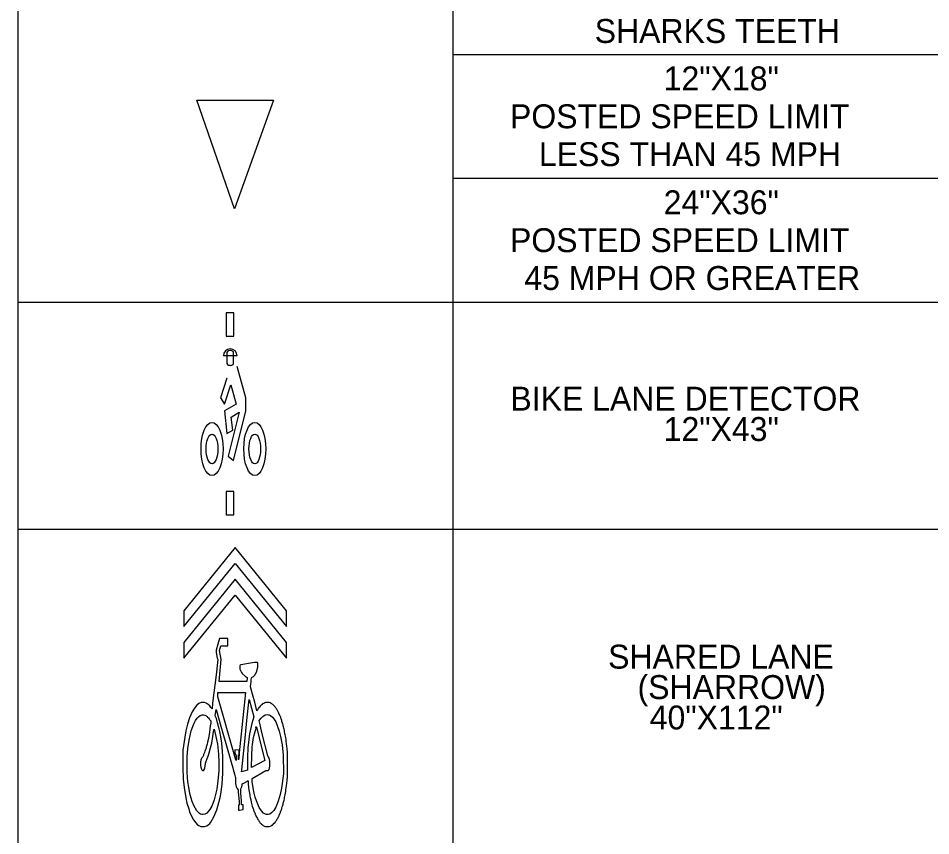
# Model space of a CAD drawing. Extents: x 9999.9 to 10007, y 10023.6 to 10033.8.
# Drawn here: x 9999.907 to 10002.196, y 10026.578 to 10028.629 of the extents above; entities that cross this region are included whole.
import ezdxf

# ---------------------------------------------------------------- set-up
doc = ezdxf.new("R2010")
doc.units = 0
for name, color, linetype in [('DETL-LINE', 7, 'Continuous'), ('DETL-NOTE', 7, 'Continuous'), ('TTLB-TEXT', 7, 'Continuous')]:
    doc.layers.add(name, color=color, linetype=linetype)

msp = doc.modelspace()

# ---------------------------------------------------------------- linework, layer by layer
at = {"layer": 'DETL-LINE'}
for p, q in [((10000.4498, 10028.151), (10000.3551, 10028.4237)), ((10000.3551, 10028.4237), (10000.5471, 10028.4237)), ((10000.5471, 10028.4237), (10000.4498, 10028.151)), ((10000.4453, 10027.7823), (10000.4216, 10027.7823))]:
    msp.add_line(p, q, dxfattribs=at)
for points in [[(10000.4306, 10027.7907), (10000.4306, 10027.763)], [(10000.4563, 10027.7823), (10000.4453, 10027.7823)], [(10000.4469, 10027.763), (10000.4469, 10027.7907)], [(10000.4306, 10027.7256), (10000.4144, 10027.6769), (10000.4241, 10027.6606), (10000.4404, 10027.7094), (10000.4536, 10027.6606), (10000.4241, 10027.6443), (10000.4306, 10027.5874), (10000.4454, 10027.5956), (10000.4416, 10027.6281), (10000.4612, 10027.6411), (10000.4339, 10027.5305), (10000.4469, 10027.5192), (10000.4778, 10027.6443), (10000.4778, 10027.6769), (10000.4566, 10027.7549)], [(10000.4803, 10026.9653), (10000.4112, 10026.9653), (10000.4159, 10027.02), (10000.4119, 10027.0426), (10000.4152, 10027.0543), (10000.4325, 10027.0543), (10000.4325, 10027.0729), (10000.412, 10027.0728), (10000.4076, 10027.0589), (10000.4033, 10027.0436), (10000.4034, 10027.0378), (10000.4065, 10027.0237), (10000.4074, 10027.0204), (10000.407, 10027.0125), (10000.4032, 10026.9814), (10000.3946, 10026.9104), (10000.3932, 10026.8962), (10000.3906, 10026.8999), (10000.3875, 10026.9038), (10000.3832, 10026.9077), (10000.3782, 10026.9108), (10000.3746, 10026.9121), (10000.3661, 10026.912), (10000.3603, 10026.9097), (10000.3553, 10026.9057), (10000.3489, 10026.8986), (10000.3432, 10026.8889), (10000.3368, 10026.8743), (10000.3315, 10026.8577), (10000.3276, 10026.841), (10000.3246, 10026.8252), (10000.3203, 10026.7931), (10000.3199, 10026.7656), (10000.3196, 10026.7501), (10000.3208, 10026.7201), (10000.323, 10026.6989), (10000.3275, 10026.6733), (10000.3301, 10026.6603), (10000.3346, 10026.6455), (10000.337, 10026.6383), (10000.3426, 10026.6256), (10000.3465, 10026.6181), (10000.3522, 10026.6105), (10000.3563, 10026.6062), (10000.3597, 10026.6036), (10000.3654, 10026.6012), (10000.3747, 10026.6012), (10000.38, 10026.6031), (10000.3833, 10026.6058), (10000.3873, 10026.6091), (10000.39, 10026.6125), (10000.3979, 10026.6258), (10000.4053, 10026.643), (10000.4105, 10026.6617), (10000.4136, 10026.6745), (10000.4159, 10026.6874), (10000.4186, 10026.708), (10000.4206, 10026.734), (10000.4206, 10026.778), (10000.4197, 10026.7893), (10000.4178, 10026.8103), (10000.4157, 10026.826), (10000.4129, 10026.8395), (10000.4115, 10026.8465), (10000.4073, 10026.8617), (10000.4041, 10026.8726), (10000.4014, 10026.8791), (10000.4037, 10026.8948), (10000.4156, 10026.853), (10000.4332, 10026.7916), (10000.4369, 10026.7776), (10000.4412, 10026.7627), (10000.4452, 10026.7488), (10000.4471, 10026.7414), (10000.4484, 10026.7368), (10000.4491, 10026.7348), (10000.4504, 10026.7301), (10000.4512, 10026.7254), (10000.4524, 10026.7254), (10000.4524, 10026.7088), (10000.4538, 10026.7015), (10000.4544, 10026.6996), (10000.4551, 10026.6982), (10000.4565, 10026.6963), (10000.4577, 10026.6942), (10000.4591, 10026.6942), (10000.4591, 10026.6876), (10000.461, 10026.6637), (10000.4616, 10026.6556), (10000.4625, 10026.655), (10000.4616, 10026.655), (10000.4597, 10026.655), (10000.4597, 10026.6424), (10000.4623, 10026.6424), (10000.471, 10026.6437), (10000.4711, 10026.6556), (10000.4671, 10026.6556), (10000.4671, 10026.6654), (10000.4664, 10026.6754), (10000.4657, 10026.6848), (10000.4656, 10026.6961), (10000.4664, 10026.6975), (10000.4671, 10026.6995), (10000.4677, 10026.7015), (10000.4684, 10026.7041), (10000.4684, 10026.708), (10000.4703, 10026.7088), (10000.4716, 10026.7095), (10000.473, 10026.7101), (10000.4763, 10026.7121), (10000.4771, 10026.7128), (10000.479, 10026.7135), (10000.4802, 10026.7141), (10000.4823, 10026.7155), (10000.4837, 10026.7161), (10000.4837, 10026.7088), (10000.485, 10026.6982), (10000.4856, 10026.6935), (10000.4863, 10026.6889), (10000.487, 10026.6849), (10000.4877, 10026.6807), (10000.4883, 10026.6775), (10000.489, 10026.6743), (10000.4903, 10026.6683), (10000.4917, 10026.6623), (10000.4943, 10026.6523), (10000.497, 10026.6444), (10000.4976, 10026.6424), (10000.4983, 10026.6405), (10000.499, 10026.6384), (10000.4996, 10026.637), (10000.5003, 10026.6351), (10000.501, 10026.6337), (10000.5016, 10026.6317), (10000.5023, 10026.6304), (10000.5032, 10026.6283), (10000.507, 10026.6211), (10000.5083, 10026.6191), (10000.5096, 10026.6171), (10000.511, 10026.6152), (10000.5115, 10026.6138), (10000.5129, 10026.6125), (10000.5143, 10026.6105), (10000.5162, 10026.6085), (10000.5176, 10026.6071), (10000.5195, 10026.6052), (10000.5215, 10026.6038), (10000.5229, 10026.6032), (10000.5241, 10026.6024), (10000.5275, 10026.6012), (10000.5368, 10026.6011), (10000.5401, 10026.6022), (10000.5415, 10026.6031), (10000.5434, 10026.6045), (10000.5447, 10026.6051), (10000.5494, 10026.6098), (10000.5514, 10026.6118), (10000.5527, 10026.6138), (10000.5534, 10026.6144), (10000.5547, 10026.6165), (10000.5558, 10026.6179), (10000.5574, 10026.6211), (10000.5587, 10026.6231), (10000.5594, 10026.6244), (10000.5601, 10026.6258), (10000.5607, 10026.6271), (10000.5613, 10026.6281), (10000.562, 10026.6304), (10000.5627, 10026.6317), (10000.5634, 10026.633), (10000.564, 10026.6351), (10000.5647, 10026.6364), (10000.5653, 10026.6384), (10000.5661, 10026.6404), (10000.5668, 10026.6418), (10000.5674, 10026.6437), (10000.568, 10026.6457), (10000.5687, 10026.6477), (10000.5693, 10026.6503), (10000.57, 10026.6523), (10000.5707, 10026.655), (10000.5714, 10026.657), (10000.572, 10026.6597), (10000.5727, 10026.6623), (10000.5733, 10026.665), (10000.574, 10026.6677), (10000.5746, 10026.671), (10000.5753, 10026.6742), (10000.576, 10026.6776), (10000.5766, 10026.6806), (10000.5774, 10026.685), (10000.5781, 10026.689), (10000.5787, 10026.6937), (10000.5794, 10026.6981), (10000.58, 10026.7035), (10000.5806, 10026.7102), (10000.5813, 10026.7167), (10000.5826, 10026.7262), (10000.5826, 10026.7867), (10000.5813, 10026.7959), (10000.5806, 10026.8031), (10000.58, 10026.8091), (10000.5793, 10026.815), (10000.5788, 10026.8196), (10000.578, 10026.8243), (10000.5773, 10026.8283), (10000.5766, 10026.8316), (10000.5761, 10026.8357), (10000.5753, 10026.8389), (10000.5747, 10026.8423), (10000.5739, 10026.8451), (10000.5734, 10026.8483), (10000.5726, 10026.851), (10000.572, 10026.8537), (10000.5713, 10026.8565), (10000.5707, 10026.8584), (10000.5701, 10026.8609), (10000.5687, 10026.8649), (10000.5681, 10026.8676), (10000.5674, 10026.8695), (10000.5667, 10026.8709), (10000.566, 10026.8729), (10000.5654, 10026.8749), (10000.5647, 10026.8769), (10000.5641, 10026.8782), (10000.5634, 10026.8802), (10000.5607, 10026.8855), (10000.5601, 10026.8875), (10000.5594, 10026.8889), (10000.5581, 10026.8908), (10000.5574, 10026.8922), (10000.5558, 10026.8955), (10000.5541, 10026.8975), (10000.5534, 10026.8988), (10000.5514, 10026.9008), (10000.5508, 10026.9022), (10000.5455, 10026.9075), (10000.5441, 10026.9081), (10000.5428, 10026.9095), (10000.5415, 10026.9101), (10000.5389, 10026.9115), (10000.5368, 10026.9122), (10000.5275, 10026.9121), (10000.5255, 10026.9115), (10000.5229, 10026.9101), (10000.5202, 10026.9088), (10000.5182, 10026.9068), (10000.5169, 10026.9062), (10000.5136, 10026.9028), (10000.5122, 10026.9008), (10000.5109, 10026.8995), (10000.5096, 10026.8975), (10000.5083, 10026.8955), (10000.507, 10026.8935), (10000.5058, 10026.8918), (10000.5003, 10026.9133), (10000.495, 10026.9333), (10000.4916, 10026.946), (10000.4896, 10026.9513), (10000.4903, 10026.958), (10000.491, 10026.9633), (10000.4917, 10026.9693), (10000.4923, 10026.9746), (10000.4936, 10026.976), (10000.4956, 10026.9772), (10000.4969, 10026.9779), (10000.5003, 10026.9813), (10000.5016, 10026.9832), (10000.5021, 10026.9845), (10000.5033, 10026.9852), (10000.5054, 10026.9913), (10000.5068, 10026.9954), (10000.5082, 10027.0012), (10000.5082, 10027.0111), (10000.5069, 10027.0125), (10000.4997, 10027.0125), (10000.4951, 10027.0118), (10000.4651, 10027.0072), (10000.4639, 10027.0057), (10000.4631, 10027.0046), (10000.4631, 10026.996), (10000.4638, 10026.9946), (10000.4645, 10026.9926), (10000.4651, 10026.9914), (10000.4664, 10026.9893), (10000.4671, 10026.988), (10000.4684, 10026.9868), (10000.4691, 10026.9855), (10000.4761, 10026.9784), (10000.4773, 10026.9776), (10000.4785, 10026.9766), (10000.4817, 10026.9753), (10000.4817, 10026.9739), (10000.4803, 10026.9653)], [(10000.4076, 10026.9323), (10000.408, 10026.9373), (10000.4152, 10026.9373), (10000.4424, 10026.9379), (10000.4772, 10026.9378), (10000.4615, 10026.7865), (10000.461, 10026.7813), (10000.4597, 10026.7683), (10000.4592, 10026.7815), (10000.461, 10026.7813), (10000.4615, 10026.7865), (10000.4611, 10026.7919), (10000.4604, 10026.7932), (10000.4504, 10026.7933), (10000.4504, 10026.7878), (10000.4513, 10026.7819), (10000.4531, 10026.7819), (10000.4537, 10026.7785), (10000.4538, 10026.7666), (10000.4524, 10026.7713), (10000.4423, 10026.8063), (10000.4162, 10026.8971), (10000.4075, 10026.9265), (10000.4076, 10026.9323)], [(10000.4674, 10026.7383), (10000.4676, 10026.7435), (10000.4761, 10026.8233), (10000.4817, 10026.8756), (10000.4859, 10026.9134), (10000.4862, 10026.9197), (10000.4984, 10026.8761), (10000.493, 10026.8599), (10000.4874, 10026.8335), (10000.4832, 10026.799), (10000.4818, 10026.775), (10000.4818, 10026.7426), (10000.4674, 10026.7383)], [(10000.3973, 10026.8398), (10000.3984, 10026.8456), (10000.4013, 10026.835), (10000.4047, 10026.8196), (10000.4067, 10026.8077), (10000.4086, 10026.791), (10000.4093, 10026.7831), (10000.4104, 10026.7615), (10000.41, 10026.7419), (10000.4079, 10026.7155), (10000.4051, 10026.695), (10000.3987, 10026.6682), (10000.3926, 10026.6521), (10000.3878, 10026.6441), (10000.3846, 10026.6397), (10000.3798, 10026.6347), (10000.3749, 10026.6321), (10000.3703, 10026.6312), (10000.3677, 10026.6316), (10000.3643, 10026.6323), (10000.3618, 10026.6341), (10000.3592, 10026.6366), (10000.3552, 10026.6403), (10000.3473, 10026.6543), (10000.3434, 10026.6637), (10000.3406, 10026.6721), (10000.3376, 10026.6839), (10000.3347, 10026.6997), (10000.3327, 10026.7134), (10000.3309, 10026.7372), (10000.3307, 10026.7762), (10000.3323, 10026.7971), (10000.3355, 10026.8179), (10000.3409, 10026.8414), (10000.3448, 10026.8526), (10000.3482, 10026.8605), (10000.3515, 10026.867), (10000.356, 10026.8734), (10000.3592, 10026.8768), (10000.3634, 10026.8797), (10000.3687, 10026.8816), (10000.3722, 10026.8817), (10000.3754, 10026.8808), (10000.3778, 10026.8794), (10000.3792, 10026.8784), (10000.3807, 10026.8771), (10000.3822, 10026.8755), (10000.3841, 10026.8738), (10000.3858, 10026.8718), (10000.387, 10026.87), (10000.3887, 10026.8677), (10000.3899, 10026.866), (10000.3898, 10026.8596), (10000.3886, 10026.8542), (10000.3867, 10026.8383), (10000.384, 10026.8224), (10000.3819, 10026.8126), (10000.3807, 10026.8075), (10000.3802, 10026.8057), (10000.3795, 10026.8028), (10000.3786, 10026.8009), (10000.3781, 10026.7982), (10000.3774, 10026.7963), (10000.3767, 10026.7942), (10000.3755, 10026.7904), (10000.3741, 10026.787), (10000.3719, 10026.7818), (10000.3714, 10026.7795), (10000.3707, 10026.7777), (10000.3701, 10026.7765), (10000.3673, 10026.7736), (10000.3667, 10026.7721), (10000.3662, 10026.7703), (10000.3653, 10026.7679), (10000.3646, 10026.7633), (10000.3646, 10026.7545), (10000.3655, 10026.7498), (10000.3661, 10026.7473), (10000.3667, 10026.7452), (10000.3674, 10026.7439), (10000.3684, 10026.7428), (10000.3695, 10026.742), (10000.3721, 10026.7421), (10000.3729, 10026.7428), (10000.3739, 10026.745), (10000.3746, 10026.7461), (10000.3754, 10026.7488), (10000.376, 10026.7528), (10000.3768, 10026.7603), (10000.3813, 10026.772), (10000.3841, 10026.7799), (10000.3861, 10026.7859), (10000.3897, 10026.7988), (10000.3923, 10026.8102), (10000.3952, 10026.8268), (10000.3973, 10026.8398)], [(10000.4942, 10026.7141), (10000.4939, 10026.7221), (10000.5282, 10026.7422), (10000.5343, 10026.7422), (10000.5362, 10026.7447), (10000.5375, 10026.7489), (10000.5382, 10026.7531), (10000.5382, 10026.7655), (10000.5375, 10026.7694), (10000.5354, 10026.7747), (10000.5342, 10026.7759), (10000.5328, 10026.7786), (10000.5192, 10026.8342), (10000.5121, 10026.8636), (10000.5115, 10026.8673), (10000.5162, 10026.8731), (10000.5207, 10026.8775), (10000.5238, 10026.8797), (10000.5268, 10026.8814), (10000.5285, 10026.8816), (10000.5316, 10026.8819), (10000.5345, 10026.8818), (10000.5369, 10026.8817), (10000.54, 10026.8796), (10000.5445, 10026.8754), (10000.548, 10026.8713), (10000.5529, 10026.8638), (10000.5569, 10026.8547), (10000.5616, 10026.8407), (10000.5653, 10026.8275), (10000.5689, 10026.8065), (10000.5714, 10026.7799), (10000.5722, 10026.7335), (10000.5674, 10026.6973), (10000.5643, 10026.682), (10000.5592, 10026.6651), (10000.5533, 10026.6502), (10000.5481, 10026.6418), (10000.5432, 10026.6365), (10000.5384, 10026.6327), (10000.534, 10026.6315), (10000.529, 10026.6316), (10000.5256, 10026.6328), (10000.5227, 10026.6349), (10000.5173, 10026.6406), (10000.5117, 10026.6494), (10000.5078, 10026.6573), (10000.5047, 10026.6659), (10000.5016, 10026.6749), (10000.4992, 10026.6849), (10000.4965, 10026.6983), (10000.4942, 10026.7141)], [(10000.4924, 10026.7496), (10000.4932, 10026.7798), (10000.4943, 10026.8006), (10000.4949, 10026.8071), (10000.4976, 10026.825), (10000.501, 10026.8396), (10000.5036, 10026.8471), (10000.5035, 10026.8511), (10000.5046, 10026.851), (10000.5182, 10026.7962), (10000.5256, 10026.7665), (10000.4924, 10026.7496)]]:
    msp.add_lwpolyline(points, dxfattribs=at)
msp.add_arc((10000.4389, 10027.7823), 0.0173, 0, 180, dxfattribs=at)
for centre, start_param, end_param in [((10000.4388, 10027.7907), 3.141585, 6.283185), ((10000.4388, 10027.763), 0, 3.1416)]:
    msp.add_ellipse(centre, major_axis=(-0.00813, 0), ratio=0.6, start_param=start_param, end_param=end_param, dxfattribs=at)
for centre, major_axis, ratio in [((10000.3932, 10027.5484), (0, -0.0667), 0.414634), ((10000.5005, 10027.5484), (0, -0.0667), 0.414634), ((10000.3932, 10027.5484), (0, -0.0374), 0.391304), ((10000.5005, 10027.5484), (0, -0.0374), 0.391304)]:
    msp.add_ellipse(centre, major_axis=major_axis, ratio=ratio, dxfattribs=at)
at = {"layer": 'DETL-NOTE'}
for p, q in [((9999.9071, 10025.0937), (9999.9071, 10033.8463)), ((10000.9969, 10033.4982), (10000.9969, 10025.0937)), ((10000.9969, 10028.5382), (10003.5339, 10028.5382)), ((10000.9969, 10028.2276), (10003.5339, 10028.2276)), ((9999.9071, 10027.9169), (10003.5339, 10027.9169)), ((9999.9071, 10027.3471), (10003.5339, 10027.3471))]:
    msp.add_line(p, q, dxfattribs=at)
at = {"layer": 'TTLB-TEXT'}
for points in [[(10000.4483, 10027.8895), (10000.4289, 10027.8895), (10000.4289, 10027.8312), (10000.4483, 10027.8312)], [(10000.4483, 10027.4416), (10000.4289, 10027.4416), (10000.4289, 10027.3833), (10000.4483, 10027.3833)]]:
    msp.add_lwpolyline(points, close=True, dxfattribs=at)
for points in [[(10000.3221, 10027.1027), (10000.4511, 10027.2614), (10000.5801, 10027.1027), (10000.5801, 10027.1423), (10000.4511, 10027.3011), (10000.3221, 10027.1423), (10000.3221, 10027.1027)], [(10000.5801, 10027.063), (10000.4511, 10027.2217), (10000.3221, 10027.063), (10000.3221, 10027.0233), (10000.4511, 10027.182), (10000.5801, 10027.0233), (10000.5801, 10027.063)]]:
    msp.add_lwpolyline(points, dxfattribs=at)

# ---------------------------------------------------------------- texts
at = {"layer": 'DETL-NOTE'}
for s, p in [('SHARKS TEETH', (10001.3532, 10028.5669)), ('12"X18"', (10001.5263, 10028.4479)), ('POSTED SPEED LIMIT', (10001.1407, 10028.3529)), ('LESS THAN 45 MPH', (10001.2132, 10028.2579)), ('24"X36"', (10001.5263, 10028.1372)), ('POSTED SPEED LIMIT', (10001.1407, 10028.0422)), ('45 MPH OR GREATER', (10001.1767, 10027.9472)), ('BIKE LANE DETECTOR', (10001.1417, 10027.6446)), ('12"X43"', (10001.5263, 10027.5683)), ('SHARED LANE', (10001.3869, 10026.9974)), ('(SHARROW)', (10001.4607, 10026.9211)), ('40"X112"', (10001.4913, 10026.8448))]:
    msp.add_text(s, height=0.06, dxfattribs=at).set_placement(p)

doc.saveas('drawing.dxf')
